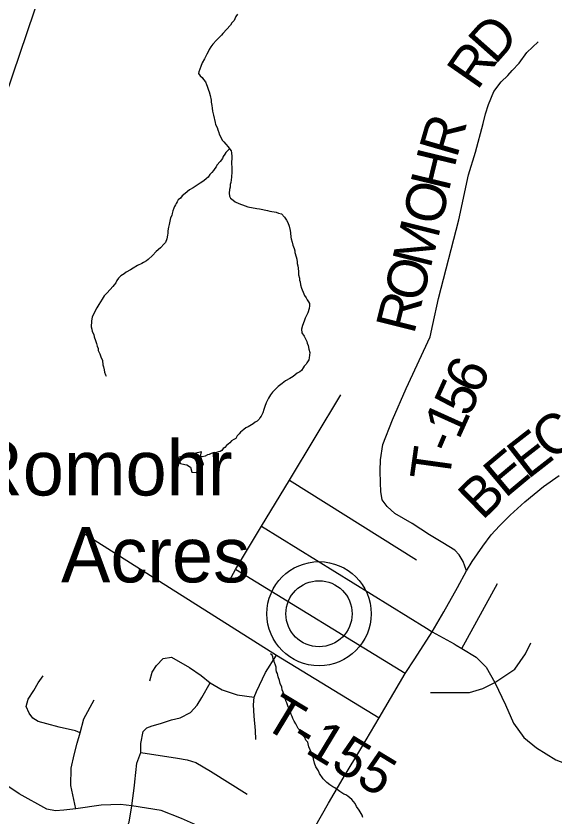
# Model space of a CAD drawing. Extents: x 44.2 to 78.2, y 4.5 to 26.5.
# Drawn here: x 49.072 to 49.842, y 19.122 to 20.266 of the extents above; entities that cross this region are included whole.
import ezdxf

# ---------------------------------------------------------------- set-up
doc = ezdxf.new("R2010")
doc.units = 0
for name, color, linetype in [('GM_X_County_Road', 7, 'Continuous'), ('GM_X_County_Road_Text', 7, 'Continuous'), ('GM_X_Minor_Lake', 7, 'Continuous'), ('GM_X_Minor_River', 7, 'Continuous'), ('GM_X_Township_Road', 7, 'Continuous'), ('GM_X_Township_Road_Text', 7, 'Continuous'), ('GM_X_Unincorporated', 7, 'Continuous'), ('GM_X_Unincorporated_Location', 7, 'Continuous'), ('GM_X_Unincorporated_Text', 7, 'Continuous'), ('SH_Data', 7, 'Continuous')]:
    doc.layers.add(name, color=color, linetype=linetype)

msp = doc.modelspace()

# ---------------------------------------------------------------- linework, layer by layer
at = {"layer": 'GM_X_County_Road'}
msp.add_lwpolyline([(49.4882, 19.0889), (49.5183, 19.1414), (49.5394, 19.1771), (49.5661, 19.2215), (49.5909, 19.2635), (49.6279, 19.327), (49.6418, 19.3476), (49.6666, 19.3864), (49.6833, 19.415), (49.7024, 19.4496), (49.7156, 19.4735), (49.7237, 19.4866), (49.7386, 19.5086), (49.7507, 19.5251), (49.7625, 19.538), (49.7777, 19.5528), (49.7987, 19.5722), (49.8253, 19.5938), (49.8476, 19.6098)], dxfattribs=at)
at = {"layer": 'GM_X_Minor_Lake'}
for points in [[(49.3356, 19.6371), (49.3369, 19.6434), (49.3033, 19.6354), (49.3048, 19.6312), (49.307, 19.627), (49.313, 19.6253), (49.316, 19.6249), (49.3213, 19.6217), (49.323, 19.6145)], [(49.323, 19.6145), (49.3295, 19.614), (49.34, 19.6255), (49.3357, 19.6371)]]:
    msp.add_lwpolyline(points, dxfattribs=at)
at = {"layer": 'GM_X_Minor_River'}
for points in [[(49.3883, 20.2687), (49.386, 20.2653), (49.3844, 20.2619), (49.3836, 20.2597), (49.3804, 20.2563), (49.3784, 20.253), (49.3675, 20.2411), (49.3656, 20.2389), (49.3605, 20.2337), (49.3582, 20.2315), (49.3531, 20.2259), (49.3503, 20.2222), (49.3479, 20.2181), (49.3463, 20.2151), (49.3447, 20.2118), (49.3411, 20.205), (49.338, 20.1994), (49.3359, 20.1941), (49.3331, 20.1863), (49.3326, 20.184), (49.3352, 20.1805), (49.3378, 20.1785), (49.34, 20.1755), (49.3426, 20.1723), (49.344, 20.1681), (49.3451, 20.1658), (49.3468, 20.1601), (49.3479, 20.1578), (49.3493, 20.1528)], [(49.3493, 20.1528), (49.3507, 20.146), (49.351, 20.1429), (49.3516, 20.1383), (49.3523, 20.1345), (49.3529, 20.1303), (49.3539, 20.1246), (49.3563, 20.1139), (49.357, 20.1113), (49.3592, 20.107), (49.3602, 20.1036), (49.3616, 20.0998), (49.3623, 20.0975), (49.3649, 20.0921), (49.3667, 20.089), (49.3689, 20.0863), (49.3719, 20.0832), (49.3752, 20.0793), (49.3774, 20.0758), (49.3792, 20.0735), (49.3799, 20.0708), (49.3801, 20.0655), (49.3799, 20.0545), (49.3801, 20.0507), (49.3804, 20.0473), (49.3804, 20.0446), (49.3803, 20.0412), (49.3798, 20.0382), (49.3798, 20.0359), (49.3788, 20.0284), (49.378, 20.0254), (49.3779, 20.0216), (49.377, 20.0182), (49.3765, 20.0129), (49.3768, 20.0087), (49.3782, 20.006), (49.382, 20.0029), (49.3849, 20.0005), (49.3902, 19.9985), (49.3992, 19.9948), (49.403, 19.9936), (49.4162, 19.9913), (49.42, 19.9905), (49.431, 19.9883), (49.4347, 19.9874), (49.4434, 19.9857), (49.4468, 19.9845), (49.4514, 19.9836), (49.4554, 19.9786), (49.4583, 19.9743), (49.4602, 19.9712), (49.4623, 19.9659), (49.4637, 19.9598), (49.464, 19.9563), (49.4646, 19.9502), (49.4649, 19.9476), (49.4663, 19.943), (49.4673, 19.9388), (49.4691, 19.9338), (49.4701, 19.9307), (49.4705, 19.9281), (49.4722, 19.9223), (49.4729, 19.9189), (49.4735, 19.9147), (49.4735, 19.9124), (49.4745, 19.9094), (49.4748, 19.906), (49.4755, 19.9006), (49.4757, 19.8965), (49.4767, 19.8915), (49.4771, 19.8888), (49.4777, 19.8862), (49.4784, 19.8823), (49.4798, 19.8774), (49.483, 19.8693), (49.4841, 19.867), (49.4863, 19.8636), (49.4881, 19.8608), (49.4899, 19.8578), (49.491, 19.8555), (49.4913, 19.852), (49.4908, 19.8483), (49.4888, 19.8419), (49.4872, 19.8392), (49.4848, 19.8344), (49.4835, 19.8302), (49.4811, 19.8238), (49.4798, 19.8189), (49.4805, 19.8136), (49.4834, 19.809), (49.4856, 19.8051), (49.4874, 19.8013), (49.4881, 19.7986), (49.4891, 19.7952), (49.4905, 19.7902), (49.4915, 19.7856), (49.4914, 19.7815), (49.4906, 19.7777), (49.4901, 19.775), (49.4874, 19.7709), (49.4865, 19.7687)], [(49.3771, 20.0762), (49.3715, 20.0711), (49.3703, 20.0688), (49.368, 20.0655), (49.3668, 20.0628), (49.3636, 20.0584), (49.3589, 20.0532), (49.3577, 20.0509), (49.3558, 20.0483), (49.3542, 20.0453), (49.3515, 20.0427), (49.3487, 20.0398), (49.3463, 20.0357), (49.344, 20.0342), (49.3401, 20.0309), (49.3351, 20.0272), (49.3293, 20.0236), (49.3251, 20.0207), (49.3197, 20.0178), (49.3135, 20.0126), (49.3092, 20.0093), (49.3068, 20.006), (49.3037, 20.0034), (49.3021, 20.0008), (49.3006, 19.9985), (49.2998, 19.9963), (49.2986, 19.994), (49.2974, 19.9914), (49.2961, 19.988), (49.2953, 19.9839), (49.2944, 19.9813), (49.2928, 19.9779), (49.2924, 19.9756), (49.2911, 19.9707), (49.2907, 19.9681), (49.2898, 19.9643), (49.2894, 19.962), (49.2889, 19.9586), (49.2889, 19.956), (49.2884, 19.953), (49.2875, 19.948), (49.2855, 19.9428), (49.2835, 19.9406), (49.2784, 19.935), (49.2722, 19.9295), (49.2671, 19.9239), (49.2606, 19.9184), (49.2586, 19.9162), (49.254, 19.914), (49.2517, 19.9126), (49.2455, 19.9097), (49.2393, 19.9061), (49.2355, 19.9035), (49.2293, 19.9002), (49.2266, 19.8977), (49.2216, 19.8948), (49.2185, 19.8914), (49.2161, 19.8884), (49.2145, 19.8851), (49.2122, 19.8821), (49.2102, 19.8795), (49.2067, 19.8754), (49.202, 19.8702), (49.1981, 19.8662), (49.1949, 19.8617), (49.1905, 19.8538), (49.1874, 19.8494), (49.1854, 19.846), (49.183, 19.8407), (49.181, 19.8366), (49.1797, 19.8302), (49.1795, 19.8222), (49.1802, 19.8188), (49.1808, 19.8154), (49.183, 19.8112), (49.1837, 19.8077), (49.1858, 19.8027), (49.1869, 19.7985), (49.1879, 19.7947), (49.1893, 19.7913), (49.1896, 19.7882), (49.1918, 19.7836), (49.1932, 19.7794), (49.1954, 19.774), (49.1963, 19.7679), (49.197, 19.7649), (49.198, 19.7607), (49.1983, 19.7573), (49.2001, 19.7534), (49.2009, 19.7517)], [(49.4865, 19.7687), (49.4838, 19.7657), (49.4822, 19.7635), (49.4799, 19.7598), (49.4775, 19.7579), (49.4737, 19.7557), (49.4679, 19.751), (49.4629, 19.7484), (49.4571, 19.7448), (49.452, 19.7411), (49.4466, 19.7367), (49.4427, 19.733), (49.4384, 19.7286), (49.4357, 19.7249), (49.4325, 19.72), (49.4293, 19.7137), (49.4273, 19.7084), (49.426, 19.7039), (49.4244, 19.6994), (49.422, 19.6945), (49.4204, 19.6923), (49.4192, 19.69), (49.4165, 19.6874), (49.4138, 19.686), (49.4107, 19.6834), (49.4034, 19.6794), (49.4003, 19.6776), (49.3976, 19.6754), (49.3929, 19.6714), (49.3909, 19.6691), (49.3878, 19.6662), (49.3858, 19.6624), (49.3831, 19.661), (49.3797, 19.6592), (49.3773, 19.6562), (49.3727, 19.6525), (49.3703, 19.6496), (49.368, 19.6481), (49.366, 19.6455), (49.3637, 19.644), (49.3614, 19.6433), (49.3572, 19.6423), (49.3549, 19.6424), (49.3507, 19.641), (49.348, 19.6399), (49.3457, 19.6392), (49.3423, 19.6374), (49.3381, 19.6364), (49.3354, 19.6372)], [(49.5673, 19.1212), (49.5666, 19.1243), (49.5622, 19.1316), (49.5582, 19.137), (49.5564, 19.1412), (49.5516, 19.147), (49.546, 19.1517), (49.5431, 19.1533), (49.5404, 19.1545), (49.5374, 19.1565), (49.5344, 19.1581), (49.5274, 19.1636), (49.5247, 19.1648), (49.5202, 19.1676), (49.5162, 19.1711), (49.5106, 19.1762), (49.5055, 19.1839), (49.504, 19.1877), (49.5004, 19.1935), (49.4983, 19.1989), (49.4955, 19.2111), (49.4923, 19.2176), (49.4905, 19.2222), (49.4891, 19.2264), (49.4888, 19.2287), (49.4862, 19.2318), (49.4844, 19.2353), (49.4803, 19.2396), (49.4788, 19.2419), (49.4767, 19.2461), (49.4752, 19.2484), (49.4716, 19.255), (49.4694, 19.2585), (49.4676, 19.2623), (49.4665, 19.2654), (49.4651, 19.2681), (49.4629, 19.2738), (49.4601, 19.2807), (49.459, 19.2849), (49.4576, 19.2876), (49.4566, 19.2922), (49.4555, 19.2956), (49.4534, 19.3002), (49.4523, 19.3033), (49.4516, 19.3071), (49.4495, 19.3125), (49.4485, 19.3167), (49.4467, 19.322), (49.4453, 19.3266), (49.4442, 19.3293), (49.4435, 19.3324), (49.4436, 19.3358), (49.4426, 19.3388), (49.4411, 19.3423), (49.4408, 19.3446), (49.4394, 19.348), (49.4387, 19.3507), (49.438, 19.353), (49.4354, 19.355)]]:
    msp.add_lwpolyline(points, dxfattribs=at)
at = {"layer": 'GM_X_Township_Road'}
for p, q in [((49.4627, 19.6032), (49.5362, 19.725)), ((49.4627, 19.6032), (49.6439, 19.4892)), ((49.4229, 19.5373), (49.6582, 19.3916)), ((49.6279, 19.327), (49.3855, 19.4753)), ((49.7086, 19.3626), (49.7596, 19.4556))]:
    msp.add_line(p, q, dxfattribs=at)
for points in [[(49.7156, 19.4735), (49.7106, 19.4868), (49.7052, 19.4965), (49.6986, 19.5031), (49.6818, 19.5135), (49.6627, 19.5248), (49.6378, 19.5411), (49.6133, 19.5555), (49.6022, 19.5656), (49.5952, 19.5748), (49.5932, 19.587), (49.5924, 19.5992), (49.592, 19.6166), (49.5928, 19.632), (49.5958, 19.6539), (49.6098, 19.6893), (49.6294, 19.7341), (49.6634, 19.8079), (49.6673, 19.8255), (49.6754, 19.8626), (49.7043, 19.9749), (49.7184, 20.0392), (49.7284, 20.0717), (49.7393, 20.1126), (49.7426, 20.1262), (49.7467, 20.1399), (49.7546, 20.1581), (49.7651, 20.172), (49.7743, 20.181), (49.7808, 20.1884), (49.7908, 20.1988), (49.8015, 20.2141), (49.8177, 20.2291)], [(49.3772, 19.4597), (49.3855, 19.4753), (49.4229, 19.5373), (49.4627, 19.6032)], [(49.171, 19.5259), (49.4443, 19.3532), (49.5909, 19.2635)], [(49.6582, 19.3916), (49.6666, 19.3864), (49.698, 19.369), (49.7005, 19.3675)], [(49.6639, 19.2998), (49.7195, 19.2995), (49.7389, 19.3055), (49.7559, 19.3142), (49.7845, 19.3328), (49.7995, 19.3548), (49.8072, 19.3705)], [(49.7005, 19.3675), (49.7086, 19.3626), (49.7291, 19.35), (49.7435, 19.3361), (49.7559, 19.3142), (49.7709, 19.2822), (49.7825, 19.2558), (49.7972, 19.2355), (49.8152, 19.2205), (49.8432, 19.2035), (49.8615, 19.1962), (49.8815, 19.1965), (49.893, 19.2015), (49.9078, 19.2099), (49.9251, 19.2229), (49.9475, 19.2428), (49.9666, 19.2576), (49.9883, 19.2727), (50.0049, 19.2786), (50.0207, 19.2805), (50.0429, 19.2758), (50.0609, 19.2703), (50.1251, 19.2548), (50.1402, 19.2515)], [(49.4144, 19.2326), (49.4142, 19.2455), (49.4124, 19.2659), (49.4111, 19.2819), (49.412, 19.293), (49.4153, 19.3012), (49.4286, 19.3284), (49.4443, 19.3532)], [(49.2631, 19.3164), (49.2667, 19.3288), (49.2726, 19.3383), (49.2822, 19.3481), (49.2942, 19.3502), (49.3198, 19.3352), (49.3363, 19.3242), (49.3492, 19.3133), (49.3667, 19.3033), (49.3881, 19.2963), (49.412, 19.293)], [(49.1635, 19.2419), (49.1571, 19.2449), (49.1337, 19.2502), (49.1161, 19.255), (49.1038, 19.2581), (49.096, 19.2631), (49.0907, 19.2701), (49.0868, 19.2798), (49.0896, 19.2901), (49.0977, 19.3024), (49.1038, 19.3136), (49.1108, 19.3236)], [(49.2564, 19.2466), (49.259, 19.2491), (49.2667, 19.2522), (49.2786, 19.2556), (49.2943, 19.2605), (49.3064, 19.2636), (49.3214, 19.271), (49.3309, 19.2816), (49.3373, 19.2927), (49.3492, 19.3133)], [(49.1575, 19.1334), (49.1502, 19.1669), (49.1507, 19.1915), (49.1552, 19.2106), (49.1596, 19.2271), (49.1635, 19.2419), (49.1688, 19.2622), (49.1839, 19.289)], [(49.2411, 19.167), (49.2417, 19.1722), (49.2446, 19.1986), (49.2501, 19.2141), (49.2505, 19.2269), (49.2538, 19.244), (49.2564, 19.2466)], [(49.2501, 19.2141), (49.3027, 19.2059), (49.3167, 19.2034), (49.3289, 19.1998), (49.3496, 19.1875), (49.402, 19.1546)], [(49.4549, 19.0327), (49.4099, 19.0615), (49.3606, 19.0927), (49.3297, 19.1102), (49.3082, 19.1195), (49.2792, 19.1312), (49.2375, 19.1379), (49.2212, 19.1397), (49.1938, 19.1389), (49.1575, 19.1334), (49.1403, 19.1314), (49.1283, 19.1307), (49.1161, 19.1332), (49.0765, 19.1551), (49.038, 19.1805), (49.0107, 19.1981)], [(49.2142, 19.082), (49.227, 19.101), (49.2335, 19.1145), (49.2375, 19.1379), (49.2411, 19.167)]]:
    msp.add_lwpolyline(points, dxfattribs=at)
at = {"layer": 'GM_X_Unincorporated'}
for radius in [0.0744, 0.0472]:
    msp.add_circle((49.5048, 19.4122), radius, dxfattribs=at)
at = {"layer": 'GM_X_Unincorporated_Location'}
msp.add_line((49.5048, 19.4122), (49.5048, 19.4122), dxfattribs=at)
at = {"layer": 'SH_Data'}
msp.add_lwpolyline([(49.0046, 20.5412), (49.7056, 22.0687), (49.0046, 19.9988)], close=True, dxfattribs=at)

# ---------------------------------------------------------------- texts
at = {"layer": 'GM_X_County_Road_Text'}
for s, rotation, p in [('C', 37.7778, (49.8363, 19.6293)), ('E', 37.9182, (49.8028, 19.6032)), ('E', 39.8901, (49.7706, 19.5763)), ('B', 44.3073, (49.7381, 19.5445))]:
    msp.add_text(s, height=0.0568, rotation=rotation, dxfattribs=at).set_placement(p)
at = {"layer": 'GM_X_Township_Road_Text'}
for s, height, rotation, p in [('D', 0.0568, 48.5002, (49.7563, 20.1955)), ('R', 0.0568, 55.1992, (49.7308, 20.1586)), ('R', 0.0568, 73.7822, (49.7015, 20.0619)), ('H', 0.0568, 76.402, (49.69, 20.014)), ('O', 0.0568, 77.4988, (49.6792, 19.9654)), ('M', 0.0568, 76.0198, (49.6639, 19.904)), ('O', 0.0568, 75.9028, (49.6517, 19.8554)), ('R', 0.0568, 75.9051, (49.6404, 19.8102)), ('6', 0.0568, 65.516, (49.7333, 19.7231)), ('5', 0.0568, 65.5509, (49.7189, 19.6913)), ('1', 0.0568, 65.7326, (49.7045, 19.6594)), ('-', 0.0568, 66.8967, (49.6955, 19.6382)), ('T', 0.0568, 82.0893, (49.6907, 19.6)), ('T-155', 0.05682, 328.7953, (49.4219, 19.2519))]:
    msp.add_text(s, height=height, rotation=rotation, dxfattribs=at).set_placement(p)
at = {"layer": 'GM_X_Unincorporated_Text'}
for s, p in [('Romohr', (49.0055, 19.5812)), ('Acres', (49.1364, 19.457))]:
    msp.add_text(s, height=0.07898, rotation=0, dxfattribs=at).set_placement(p)

doc.saveas('drawing.dxf')
